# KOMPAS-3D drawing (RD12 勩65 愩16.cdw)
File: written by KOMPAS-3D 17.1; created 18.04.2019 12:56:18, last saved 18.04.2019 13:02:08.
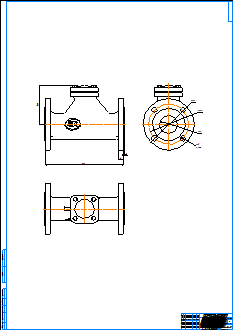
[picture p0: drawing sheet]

Sheet 1: A0, portrait

Title block, sheet 1: name: RD12 Ду65 Ру16; material: Внимание! Данный продукт является объектом авторского права ООО «Торговый Дом АДЛ». / Запрещается изменение, копирование, распространение / (в том числе путем копирования на другие сайты и ресурсы в Интернете) / или любое иное использование информации и объектов без предварительного / согласия правообладателя (ООО «Торговый Дом АДЛ»).; mass: 21,89; sheets: 1; organisation: ООО "Торговый дом АДЛ"; sheet format: A0

Views: Вид 1, Проекционный вид 2, Проекционный вид 3
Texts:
  user
Dimensions and other numbers on the sheet: 140; 19; 3; 284; 185; 145; 65; 4 отв.; 1:1; 1; 21,89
